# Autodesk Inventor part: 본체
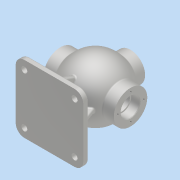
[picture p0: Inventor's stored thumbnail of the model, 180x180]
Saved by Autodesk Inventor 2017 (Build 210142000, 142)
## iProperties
Part Number: 본체
Material: 알루미늄 6061
Document SubType Name: Modeling
Designer: MRC
Density: 2.7 g/cm^3
Appearance: 알루미늄 - 평지
Mass: 1526.73 g
Surface Area: 1173.98 cm^2
Volume: 565.456 cm^3
Author: MRC
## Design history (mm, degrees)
sketch "스케치1"
  geometry: L1 (0, 54)-(0, -54); A1 r 54 centre (0, 0) between (0, -54) and (0, 54); 1 further point
  constraints: 2 end point, 2 point on circle, 1 centre point, 1 coincident, 1 midpoint, 1 vertical
  dimensions: "d0" = 108 diameter of A1
revolve "회전1" sketch "스케치1" stored, may be unused: angle "d1" = 90 deg
feature "쉘1" dims "d2" = 10
node "작업 평면1"
sketch "스케치2"
  geometry: C1 r 31 at (0, 0); 1 further point
  constraints: 1 centre point, 1 coincident
  dimensions: "d4" = 62 diameter of C1
extrude "돌출1" join sketch "스케치2" stored distance "d5" = 10; taper "d6" = 0 deg
sketch "스케치3"
  geometry: C1 r 31 at (0, 0) reference; C2 r 17.5 at (0, 0)
  constraints: 1 centre point, 1 coincident
  dimensions: "d7" = 35 diameter of C2
extrude "돌출2" cut sketch "스케치3" distance "d8" = 16; taper "d9" = 0 deg
sketch "스케치4"
  geometry: C1 r 17.5 at (0, 0) reference; C2 r 15 at (0, 0)
  constraints: 1 centre point, 1 coincident
  dimensions: "d10" = 30 diameter of C2
extrude "돌출3" cut sketch "스케치4" stored distance "d11" = 16; taper "d12" = 0 deg
sketch "스케치5" dims "d13" = 48
  geometry: C1 r 17.5 at (0, 0) reference; C2 r 31 at (0, 0) reference; 2 further points
  constraints: 2 vertical alignment, 1 coincident, 2 other
hole "구멍1" sketch "스케치5" at (0, 24) diameter "d14" = 3.242; stored, may be unused: countersink angle "d18" = 90 deg, drill point angle "d20" = 118 deg; dims "d15" = 12, "d16" = 4, "d17" = 2, "d19" = 15
node "작업 평면2"
sketch "스케치6"
  geometry: C1 r 27 at (0, 0); 1 further point
  constraints: 1 centre point, 1 coincident
  dimensions: "d25" = 54 diameter of C1
extrude "돌출4" join sketch "스케치6" stored distance "d26" = 16; taper "d27" = 0 deg
sketch "스케치7"
  geometry: C1 r 27 at (0, 0) reference; C2 r 13 at (0, 0)
  constraints: 1 centre point, 1 coincident
  dimensions: "d28" = 26 diameter of C2
extrude "돌출5" cut sketch "스케치7" stored distance "d29" = 16; taper "d30" = 0 deg
sketch "스케치8" dims "d31" = 40
  geometry: C1 r 13 at (0, 0) reference; C2 r 27 at (0, 0) reference; 2 further points
  constraints: 2 vertical alignment, 1 coincident, 2 other
hole "구멍2" sketch "스케치8" at (0, 20) diameter "d32" = 3.242; stored, may be unused: countersink angle "d36" = 90 deg, drill point angle "d38" = 118 deg; dims "d33" = 9, "d34" = 4, "d35" = 2, "d37" = 11
node "작업 평면3"
sketch "스케치9"
  geometry: L1 (62.5, 62.5)-(-62.5, 62.5); L2 (-62.5, 62.5)-(-62.5, -62.5); L3 (-62.5, -62.5)-(62.5, -62.5); L4 (62.5, -62.5)-(62.5, 62.5); L5 (62.5, 62.5)-(-62.5, -62.5); L6 (-62.5, 62.5)-(62.5, -62.5); 1 further point
  constraints: 12 end point, 2 midpoint, 2 parallel, 1 horizontal, 1 perpendicular
  dimensions: "d43" = 125 distance of L3.end L2.end; "d44" = 125 distance of L2.end L1.end
extrude "돌출6" join sketch "스케치9" distance "d45" = 10; taper "d46" = 0 deg
fillet "모깎기1" dims "d49" = 16
fillet "모깎기2" dims "d50" = 3
sketch "스케치11"
  geometry: L1 (-50.5, 4)-(50.5, 4); L2 (50.5, 4)-(50.5, -4); L3 (50.5, -4)-(-50.5, -4); L4 (-50.5, -4)-(-50.5, 4); L5 (-50.5, 4)-(50.5, -4); L6 (50.5, 4)-(-50.5, -4); L7 (-62.5, 46.5)-(-62.5, -46.5) reference; 1 further point
  constraints: 12 end point, 2 midpoint, 2 parallel, 1 horizontal, 1 perpendicular
  dimensions: "d51" = 8 distance of L1.end L2.end; "d52" = 12 distance between parallel lines of L4 L7
extrude "돌출7" join sketch "스케치11" stored distance "d53" = 10; taper "d54" = 0 deg
feature "면 기울기1" dims angle "d55" = 20 deg
sketch "스케치13"
  geometry: L1 (-75, -50.5)-(-50.221, -41.481); L2 (-75, -46.5)-(-75, -59.5) reference; L3 (-78, -62.5)-(-85, -62.5) reference; 1 further point
  constraints: 2 end point, 1 point on line
  dimensions: "d56" = 20 deg angle of L1 L3; "d57" = 12 distance from line of L3 L1.start
feature "리브1" sketch "스케치13" dims "d58" = 1, "d59" = 8, "d60" = 0, "d61" = 0, "d62" = 1, "d63" = 1
sketch "스케치14"
  geometry: C1 r 5.5 at (-46.5, -46.5); C2 r 5.5 at (-46.5, 46.5); C3 r 5.5 at (46.5, 46.5); C4 r 5.5 at (46.5, -46.5); A1 r 13 centre (-46.5, 46.5) between (-46.5, 59.5) and (-59.5, 46.5) reference; A2 r 13 centre (-46.5, -46.5) between (-59.5, -46.5) and (-46.5, -59.5) reference; A3 r 13 centre (46.5, 46.5) between (59.5, 46.5) and (46.5, 59.5) reference; A4 r 16 centre (46.5, -46.5) between (46.5, -62.5) and (62.5, -46.5) reference; 1 further point
  constraints: 4 centre point, 4 coincident
  dimensions: "d64" = 11 diameter of C1; "d65" = 11 diameter of C2; "d66" = 11 diameter of C3; "d67" = 11 diameter of C4
extrude "돌출8" cut sketch "스케치14" stored distance "d68" = 10; taper "d69" = 0 deg
chamfer "모따기1" distance "d70" = 1; stored, may be unused: second distance "d71" = 2, angle "d72" = 45 deg
fillet "모깎기3" dims "d73" = 3
fillet "모깎기4" dims "d74" = 3
chamfer "모따기2" distance "d75" = 1; stored, may be unused: second distance "d76" = 2, angle "d77" = 45 deg
fillet "모깎기5" dims "d78" = 3
chamfer "모따기3" distance "d79" = 1; stored, may be unused: second distance "d80" = 2, angle "d81" = 45 deg
fillet "모깎기6" dims "d82" = 3
fillet "모깎기7" dims "d83" = 3
fillet "모깎기8" dims "d84" = 0.6
fillet "모깎기9" dims "d85" = 0.6
node "작업 평면4"
sketch "스케치16"
  geometry: L1 (-27, 65)-(27, 65) reference; 2 further points
  constraints: 1 vertical alignment, 1 other
  dimensions: "d87" = 9 distance from line of point (0, 56) L1
feature "엠보싱1" sketch "스케치16" dims "d0" = 108, "d88" = 0.5, "d89" = 0
fillet "모깎기10" dims "d90" = 3
node "솔리드1"
pattern_circular "원형 패턴1" dims angle "d22" = 360 deg
mirror "미러1"
pattern_circular "원형 패턴2" dims angle "d40" = 360 deg
mirror "미러2"
other parameters: "d3" = 65, "d24" = 65, "d42" = -85, "d86" = -45.75
